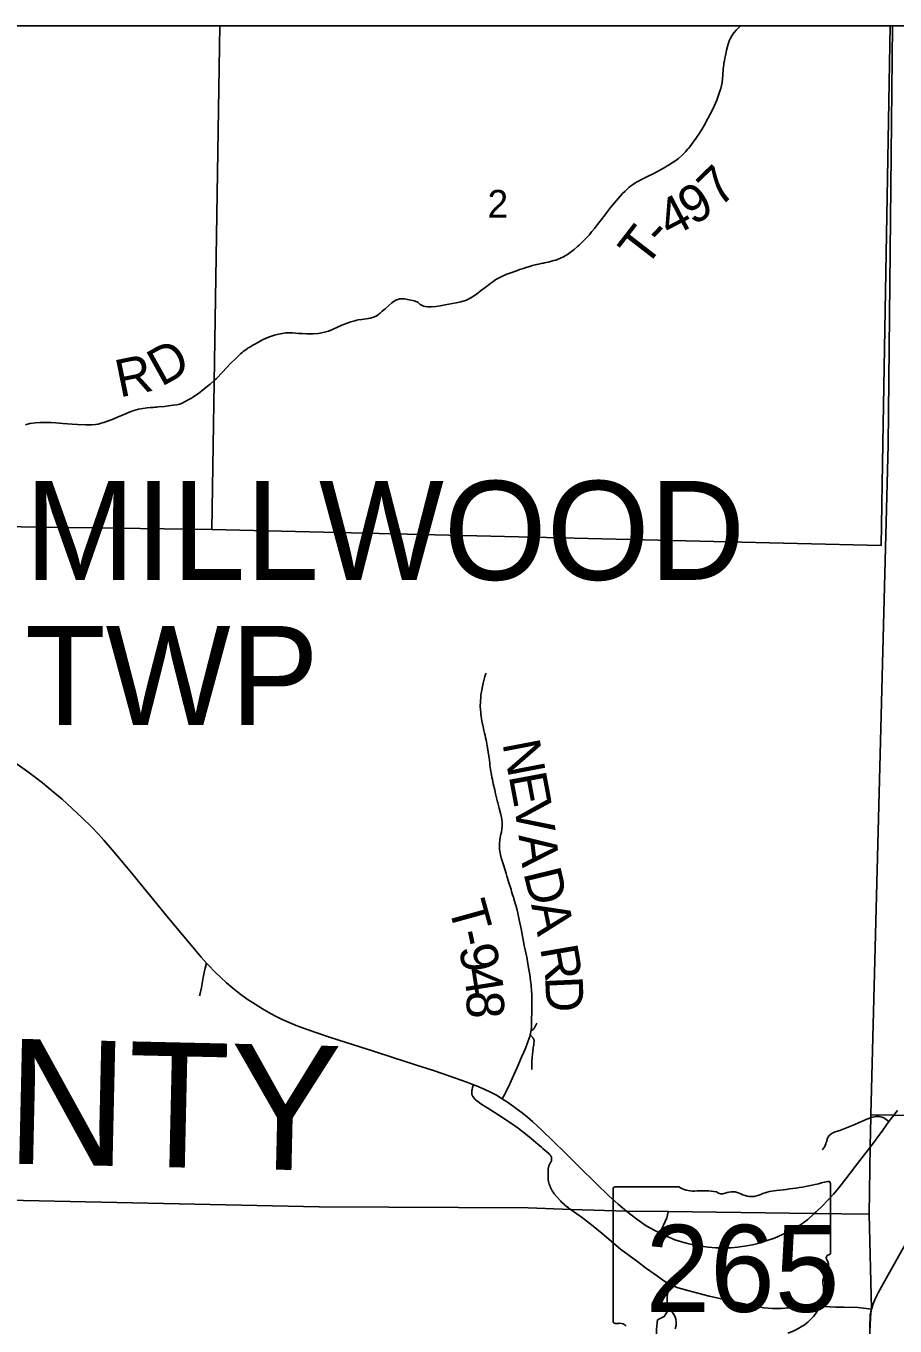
# Model space of a CAD drawing. Extents: x 0 to 34, y 0 to 22.
# Drawn here: x 5.917 to 7.235, y 18.929 to 20.9 of the extents above; entities that cross this region are included whole.
import ezdxf

# ---------------------------------------------------------------- set-up
doc = ezdxf.new("R2010")
doc.units = 0
for name, color, linetype in [('GM_X_Corporation', 7, 'Continuous'), ('GM_X_County_Text', 7, 'Continuous'), ('GM_X_Section_Text', 7, 'Continuous'), ('GM_X_State_Location', 7, 'Continuous'), ('GM_X_State_Route', 7, 'Continuous'), ('GM_X_State_Shield', 7, 'Continuous'), ('GM_X_Township_Road', 7, 'Continuous'), ('GM_X_Township_Road_Text', 7, 'Continuous'), ('GM_X_Township_Text', 7, 'Continuous'), ('SH_Data', 7, 'Continuous')]:
    doc.layers.add(name, color=color, linetype=linetype)

msp = doc.modelspace()

# ---------------------------------------------------------------- linework, layer by layer
at = {"layer": 'GM_X_Corporation'}
for points in [[(6.2111, 20.9), (5.1978, 20.9), (5.1859, 20.1511), (6.1991, 20.1367)], [(7.2273, 20.9), (6.2111, 20.9), (6.1991, 20.1367), (7.2139, 20.1126), (7.2163, 20.2673)], [(7.1227, 14.1), (8.9, 14.1), (8.9, 20.9), (7.231, 20.9), (7.2244, 20.2649), (7.1982, 19.2496), (7.1981, 19.2461), (7.1974, 19.2018), (7.1957, 19.0991), (7.1992, 18.9556), (7.197, 18.9465), (7.1949, 18.8464), (7.1846, 18.5133), (7.1817, 18.3306), (7.1804, 18.2238), (7.1572, 17.4131), (7.1504, 16.6562), (7.1434, 16.3848), (7.1318, 15.4937)], [(8.9, 19.2243), (8.9, 20.9), (7.231, 20.9), (7.2244, 20.2649), (7.1982, 19.2496), (7.2323, 19.2489), (7.3421, 19.2478), (7.6914, 19.2442), (7.7835, 19.2432)]]:
    msp.add_lwpolyline(points, close=True, dxfattribs=at)
at = {"layer": 'GM_X_State_Route'}
for points in [[(5.8954, 19.7869), (5.9197, 19.7697), (5.9318, 19.761), (5.9421, 19.753), (5.9555, 19.7419), (5.972, 19.7278), (5.9872, 19.7141), (6.003, 19.6992), (6.0163, 19.6861), (6.027, 19.675), (6.0354, 19.6658), (6.048, 19.6512), (6.0747, 19.6193), (6.095, 19.5945)], [(6.095, 19.5945), (6.1108, 19.5751), (6.1334, 19.5477), (6.1651, 19.5095), (6.1829, 19.4887), (6.1911, 19.4795), (6.1941, 19.4762), (6.2035, 19.4663), (6.2124, 19.4575), (6.2211, 19.4496), (6.2307, 19.4415), (6.241, 19.4335), (6.2526, 19.4251), (6.2645, 19.4172), (6.2756, 19.4102), (6.2842, 19.4052), (6.2947, 19.3997), (6.3058, 19.3942), (6.316, 19.3895), (6.327, 19.3851), (6.3433, 19.379), (6.3757, 19.3679), (6.3916, 19.3625), (6.4443, 19.3459), (6.4733, 19.3365), (6.5064, 19.3259), (6.5365, 19.316), (6.5683, 19.3053), (6.5858, 19.299), (6.5957, 19.2952), (6.6003, 19.2934), (6.6117, 19.2886), (6.6217, 19.2838), (6.6305, 19.2792), (6.6393, 19.2738), (6.6488, 19.2676), (6.6604, 19.2593), (6.6693, 19.2527), (6.6775, 19.2461), (6.6859, 19.2388), (6.6995, 19.2261), (6.7347, 19.1919), (6.7558, 19.1709), (6.781, 19.146), (6.8011, 19.1266), (6.8149, 19.114), (6.8282, 19.1028)], [(7.1976, 19.2012), (7.2163, 19.2264), (7.2257, 19.2392), (7.2387, 19.2562)], [(7.2, 18.9571), (7.2002, 18.9582), (7.2019, 18.9631), (7.2043, 18.969), (7.2067, 18.9745), (7.2092, 18.9796), (7.2221, 19.0025), (7.2453, 19.0437), (7.2581, 19.0668), (7.2751, 19.0967), (7.2881, 19.1201), (7.299, 19.1387), (7.3085, 19.1542), (7.3147, 19.1649), (7.3202, 19.175), (7.3242, 19.1834), (7.3275, 19.1912), (7.3306, 19.1997), (7.3336, 19.2087), (7.3364, 19.2185), (7.3385, 19.2275), (7.3402, 19.2356), (7.3415, 19.2442), (7.3427, 19.2553)], [(7.1117, 19.0994), (7.1152, 19.1025), (7.1252, 19.1119), (7.1322, 19.119), (7.1414, 19.1292), (7.1499, 19.1391), (7.1604, 19.1523), (7.1813, 19.1802), (7.1976, 19.2012)], [(6.8282, 19.1028), (6.8433, 19.0913), (6.8575, 19.0815), (6.8781, 19.0703), (6.8855, 19.0666), (6.8921, 19.0639), (6.9011, 19.0603), (6.9113, 19.0571), (6.9222, 19.054), (6.9338, 19.0516), (6.9518, 19.0489), (6.9632, 19.048), (6.9753, 19.0477), (6.9857, 19.048), (6.996, 19.049), (7.0065, 19.0503), (7.0188, 19.0526), (7.0307, 19.0555), (7.0408, 19.0588), (7.0519, 19.0626), (7.0644, 19.0679), (7.0739, 19.0726), (7.0836, 19.0782), (7.0915, 19.083), (7.1026, 19.0907), (7.1117, 19.0994)], [(7.1966, 18.921), (7.1971, 18.9313), (7.1978, 18.9417), (7.1984, 18.9489), (7.1994, 18.9551), (7.2, 18.9571)]]:
    msp.add_lwpolyline(points, dxfattribs=at)
at = {"layer": 'GM_X_State_Shield'}
for p, q in [((6.8074, 19.1369), (6.8074, 18.9368)), ((6.9072, 19.1403), (6.8107, 19.1403)), ((7.137, 19.0406), (7.137, 19.1453)), ((7.137, 19.0406), (7.137, 19.0406))]:
    msp.add_line(p, q, dxfattribs=at)
for centre, major_axis, start_param, end_param in [((6.8112, 19.1373), (0.00382, 0), 1.712693, 3.28349), ((6.9302, 19.1636), (0.037, 0), 4.042523, 4.731795), ((6.9424, 19.028), (0.133, 0), 1.404758, 1.657858), ((6.9883, 19.1152), (0.0222, 0), 0.950623, 2.079405), ((7.0642, 19.0792), (0.0703, 0), 1.699011, 2.107814), ((7.0196, 19.4132), (0.3495, 0), 4.814394, 5.042369), ((7.1333, 19.1457), (0.00367, 0), 6.141152, 7.989035), ((6.9726, 19.1384), (0.0107, 0), 3.836095, 5.185415), ((7.017, 19.147), (0.0267, 0), 4.081561, 5.145723), ((7.1361, 19.0329), (0.00568, 0), 1.883978, 3.671073), ((7.1331, 19.0402), (0.00393, 0), 5.05454, 6.418171), ((7.1, 19.0197), (0.0341, 0), 5.934695, 6.695948), ((7.1501, 18.9968), (0.0248, 0), 2.387724, 3.262537), ((7.0392, 18.9835), (0.0874, 0), 5.101752, 6.440018), ((6.8112, 18.9363), (0.00385, 0), 3.00124, 4.508301), ((6.8118, 18.9568), (0.0294, 0), 4.665946, 4.897461), ((6.8178, 18.9252), (0.0106, 0), 0.519207, 1.627899)]:
    msp.add_ellipse(centre, major_axis=major_axis, ratio=0.8, start_param=start_param, end_param=end_param, dxfattribs=at)
at = {"layer": 'GM_X_Township_Road'}
for points in [[(5.9162, 20.2956), (5.9228, 20.2972), (5.9314, 20.2986), (5.9382, 20.299), (5.9419, 20.299), (5.945, 20.299), (5.9487, 20.2988), (5.9555, 20.2988), (5.9617, 20.2985), (5.9679, 20.2981), (5.9728, 20.2975), (5.9874, 20.2963), (5.9952, 20.2958), (6.0079, 20.2953), (6.0164, 20.2953), (6.0224, 20.2958), (6.0267, 20.2965), (6.0314, 20.2977), (6.035, 20.2988), (6.0408, 20.3009), (6.0478, 20.3035), (6.0557, 20.3069), (6.0619, 20.3097), (6.0669, 20.3118), (6.075, 20.3151), (6.0808, 20.3171), (6.088, 20.319), (6.0941, 20.3201), (6.1008, 20.321), (6.1057, 20.3215), (6.11, 20.3219), (6.1125, 20.3221), (6.1155, 20.3223), (6.118, 20.3225), (6.1272, 20.3233), (6.1332, 20.324), (6.1399, 20.325), (6.1461, 20.3259), (6.1498, 20.3268), (6.1528, 20.328), (6.1642, 20.3339), (6.1679, 20.336), (6.1712, 20.3378), (6.1748, 20.3402), (6.1788, 20.3431), (6.1876, 20.3499), (6.1942, 20.3553), (6.1965, 20.3571), (6.202, 20.362), (6.206, 20.3658), (6.2149, 20.3753), (6.2274, 20.3883), (6.2357, 20.3966), (6.2382, 20.3991), (6.2399, 20.4007), (6.2408, 20.4014), (6.2425, 20.403), (6.2443, 20.4046), (6.2466, 20.4065), (6.248, 20.4076), (6.2505, 20.4093), (6.2523, 20.4107), (6.2533, 20.4114), (6.2554, 20.4126), (6.2623, 20.4167), (6.266, 20.4188), (6.2676, 20.4197), (6.2697, 20.4209), (6.2724, 20.4223), (6.275, 20.4238), (6.2777, 20.4253), (6.2788, 20.4258), (6.2877, 20.4292), (6.294, 20.4312), (6.2999, 20.4327), (6.3059, 20.4341), (6.3107, 20.4349), (6.3151, 20.4351), (6.3212, 20.4349), (6.3305, 20.4341), (6.3367, 20.4337), (6.3429, 20.4333), (6.3478, 20.4333), (6.3526, 20.4333), (6.3601, 20.4338), (6.3631, 20.4342), (6.3698, 20.4357), (6.3757, 20.4376), (6.3821, 20.4401), (6.3905, 20.444), (6.3984, 20.4476), (6.4095, 20.4514), (6.416, 20.4533), (6.4186, 20.454), (6.4207, 20.4545), (6.4263, 20.4553), (6.4362, 20.4565), (6.4398, 20.4572), (6.444, 20.4584), (6.4479, 20.4602), (6.4515, 20.4626), (6.4529, 20.4637), (6.4543, 20.4648), (6.4575, 20.4677), (6.4617, 20.4714), (6.4674, 20.4762), (6.4719, 20.4804), (6.4755, 20.483), (6.4782, 20.4845), (6.481, 20.4856), (6.4841, 20.4863), (6.4871, 20.4865), (6.4909, 20.4863), (6.4958, 20.4855), (6.5006, 20.4844), (6.5061, 20.4833), (6.5084, 20.4826), (6.5101, 20.4818), (6.5116, 20.4808), (6.5148, 20.4779), (6.5169, 20.4766), (6.5198, 20.4753), (6.5228, 20.4746), (6.5265, 20.4742), (6.5314, 20.4742), (6.5388, 20.4747), (6.545, 20.4756), (6.5529, 20.4772), (6.5693, 20.4804), (6.5766, 20.4821), (6.5795, 20.4828), (6.5819, 20.4835), (6.5853, 20.4846), (6.5887, 20.4862), (6.5919, 20.4881), (6.5956, 20.4904), (6.5976, 20.4918), (6.5996, 20.4932), (6.6026, 20.4955), (6.6055, 20.4977), (6.6085, 20.5), (6.6109, 20.5018), (6.6139, 20.5041), (6.6168, 20.5063), (6.6193, 20.5081), (6.6218, 20.5099), (6.6248, 20.512), (6.6298, 20.5156), (6.6345, 20.5184), (6.6405, 20.5214), (6.6462, 20.5238), (6.6538, 20.5263), (6.6607, 20.529), (6.6624, 20.5296), (6.6636, 20.5301), (6.6653, 20.5307), (6.6677, 20.5315), (6.6694, 20.532), (6.6741, 20.5335), (6.6823, 20.5361), (6.6852, 20.5369), (6.6894, 20.5379), (6.6917, 20.5385), (6.6986, 20.54), (6.7008, 20.5404), (6.7019, 20.5406), (6.7035, 20.5409), (6.7059, 20.5414), (6.7088, 20.5421), (6.7112, 20.5426), (6.7142, 20.5434), (6.7177, 20.5444), (6.7206, 20.5452), (6.7241, 20.5465), (6.7275, 20.5478), (6.732, 20.55), (6.7347, 20.5515), (6.7384, 20.5537), (6.7425, 20.5565), (6.7444, 20.558), (6.7484, 20.561), (6.7536, 20.5655), (6.7558, 20.5675), (6.7585, 20.5701), (6.7621, 20.5736), (6.7655, 20.5771), (6.7685, 20.5803), (6.7714, 20.5835), (6.7738, 20.5864), (6.7753, 20.5883), (6.7792, 20.5931), (6.7808, 20.595), (6.7838, 20.599), (6.7947, 20.6132), (6.7989, 20.6187), (6.8034, 20.6246), (6.8124, 20.6356), (6.8186, 20.6427), (6.8218, 20.646), (6.8255, 20.6498), (6.8315, 20.6552), (6.834, 20.6573), (6.8369, 20.6594), (6.8404, 20.6617), (6.8437, 20.6637), (6.8513, 20.6679), (6.8597, 20.672), (6.8692, 20.6766), (6.8736, 20.6788), (6.8768, 20.6806), (6.8784, 20.6814), (6.8848, 20.685), (6.8879, 20.6869), (6.8916, 20.6891), (6.8984, 20.6935), (6.9025, 20.6963), (6.9065, 20.6992), (6.9116, 20.7037), (6.9143, 20.7063), (6.9172, 20.7094), (6.9209, 20.7136), (6.9221, 20.715), (6.9237, 20.7169), (6.929, 20.7238), (6.933, 20.7295), (6.9351, 20.7326), (6.9376, 20.7362), (6.9419, 20.7432), (6.9454, 20.7492), (6.9511, 20.7598), (6.9564, 20.7697), (6.9607, 20.7786), (6.9627, 20.7831), (6.9646, 20.7877), (6.9664, 20.7923), (6.9694, 20.801), (6.9707, 20.8052), (6.972, 20.8099), (6.9727, 20.8142), (6.9736, 20.8252), (6.9744, 20.8351), (6.9748, 20.8388), (6.9751, 20.8406), (6.9754, 20.8431), (6.9758, 20.8455), (6.9761, 20.8474), (6.9768, 20.851), (6.9776, 20.8552), (6.9793, 20.8631), (6.9809, 20.8691), (6.9836, 20.8773), (6.9852, 20.8814), (6.9874, 20.8852), (6.9906, 20.8897), (6.9938, 20.8935), (6.9973, 20.897), (7.0007, 20.9)], [(6.683, 19.377), (6.6835, 19.3838), (6.6838, 19.3919), (6.6842, 19.4074), (6.6844, 19.418), (6.6843, 19.4285), (6.6842, 19.4328), (6.6839, 19.4366), (6.6831, 19.4464), (6.6823, 19.4524), (6.6811, 19.4615), (6.6788, 19.4756), (6.6765, 19.4885), (6.6755, 19.4933), (6.6728, 19.5061), (6.6711, 19.5146), (6.6678, 19.5317), (6.6652, 19.5451), (6.663, 19.5554), (6.6614, 19.562), (6.6599, 19.5672), (6.6591, 19.5701), (6.6581, 19.5736), (6.6571, 19.5771), (6.6563, 19.5795), (6.6551, 19.5829), (6.654, 19.5864), (6.6535, 19.5882), (6.6527, 19.5911), (6.6518, 19.594), (6.6509, 19.597), (6.65, 19.5999), (6.6465, 19.6112), (6.6451, 19.6153), (6.641, 19.6283), (6.6378, 19.639), (6.6366, 19.6437), (6.6354, 19.6517), (6.635, 19.6566), (6.635, 19.6597), (6.6359, 19.6671), (6.6374, 19.675), (6.638, 19.678), (6.6388, 19.6829), (6.6393, 19.6878), (6.6393, 19.6922), (6.6388, 19.6971), (6.6382, 19.7001), (6.6372, 19.7048), (6.6347, 19.7144), (6.6326, 19.7222), (6.6322, 19.724), (6.6312, 19.7282), (6.6293, 19.736), (6.6279, 19.742), (6.6257, 19.751), (6.6243, 19.7577), (6.6236, 19.7607), (6.6228, 19.765), (6.6216, 19.7729), (6.6212, 19.776), (6.6207, 19.7803), (6.6204, 19.7827), (6.6194, 19.7907), (6.6191, 19.7931), (6.6185, 19.7967), (6.6177, 19.8021), (6.6171, 19.8057), (6.6169, 19.8069), (6.6166, 19.8087), (6.616, 19.8117), (6.6148, 19.8177), (6.614, 19.8213), (6.6132, 19.8249), (6.6125, 19.828), (6.6115, 19.8322), (6.6103, 19.8376), (6.6086, 19.8462), (6.6079, 19.8504), (6.6075, 19.8535), (6.6071, 19.8566), (6.6067, 19.8596), (6.606, 19.8683), (6.6061, 19.8758), (6.6067, 19.8832), (6.6071, 19.8862), (6.6078, 19.8905), (6.6083, 19.8935), (6.6089, 19.8965), (6.6104, 19.9038), (6.612, 19.9098), (6.6131, 19.914), (6.614, 19.9169), (6.6148, 19.9192)], [(6.1804, 19.4297), (6.1814, 19.4334), (6.1833, 19.4425), (6.1858, 19.4579), (6.1872, 19.4652), (6.189, 19.4718), (6.1911, 19.4795)], [(6.6393, 19.2738), (6.6431, 19.2808), (6.6443, 19.2829), (6.647, 19.2885), (6.6486, 19.2919), (6.6567, 19.31), (6.6617, 19.3214), (6.6683, 19.3367), (6.672, 19.3446), (6.675, 19.3518), (6.6777, 19.3586), (6.6803, 19.3659), (6.6811, 19.3681), (6.6818, 19.3707)], [(6.6818, 19.3707), (6.6822, 19.3721), (6.6829, 19.3758), (6.683, 19.377)], [(6.6845, 19.3181), (6.6844, 19.319), (6.6843, 19.3206), (6.6842, 19.3268), (6.6842, 19.331), (6.6846, 19.3365), (6.6852, 19.3414), (6.6857, 19.3457), (6.6864, 19.3512), (6.6869, 19.3541), (6.687, 19.3553), (6.6874, 19.3589), (6.6875, 19.3608), (6.6875, 19.362), (6.6873, 19.3629), (6.6871, 19.3637), (6.6867, 19.3645), (6.6863, 19.3653), (6.6859, 19.3658), (6.6855, 19.3665), (6.6818, 19.3707)], [(6.683, 19.377), (6.6838, 19.3773), (6.6848, 19.3778), (6.6859, 19.3786), (6.6864, 19.3791), (6.6869, 19.3797), (6.6875, 19.3805), (6.688, 19.3813), (6.6917, 19.3884)], [(6.6273, 19.2534), (6.6215, 19.2571), (6.6068, 19.2664), (6.6022, 19.2696), (6.6004, 19.2711), (6.5989, 19.2724), (6.5977, 19.2735), (6.5967, 19.2746), (6.5949, 19.2772), (6.5943, 19.2783), (6.5939, 19.2794), (6.5934, 19.2805), (6.5931, 19.2817), (6.593, 19.2825), (6.593, 19.2841), (6.5932, 19.2862), (6.5935, 19.2879), (6.5943, 19.2908), (6.5954, 19.294), (6.5957, 19.2952)], [(6.7438, 19.1055), (6.7415, 19.1072), (6.7396, 19.1086), (6.7364, 19.1111), (6.7343, 19.1128), (6.7325, 19.1144), (6.7304, 19.1163), (6.7281, 19.1186), (6.7223, 19.1251), (6.7183, 19.1299), (6.7164, 19.1325), (6.7152, 19.1345), (6.714, 19.1364), (6.713, 19.1383), (6.7121, 19.1403), (6.7114, 19.1423), (6.7107, 19.1444), (6.7102, 19.1464), (6.7097, 19.1483), (6.7092, 19.1508), (6.709, 19.153), (6.7089, 19.1556), (6.7089, 19.1631), (6.709, 19.1647), (6.709, 19.1663), (6.709, 19.1673), (6.7091, 19.1684), (6.7093, 19.1694), (6.7095, 19.1705), (6.7098, 19.1714), (6.7102, 19.1725), (6.7106, 19.1734), (6.711, 19.1744), (6.7125, 19.1772), (6.7129, 19.178), (6.7133, 19.1788), (6.7138, 19.18), (6.7141, 19.181), (6.7142, 19.1819), (6.7142, 19.183), (6.7141, 19.1841), (6.7138, 19.1852), (6.7134, 19.1863), (6.7128, 19.1872), (6.7122, 19.1882), (6.7114, 19.1891), (6.7105, 19.1902), (6.7094, 19.1912), (6.705, 19.1952), (6.7008, 19.1987), (6.6989, 19.2003), (6.6956, 19.2031), (6.6938, 19.2048), (6.6834, 19.2136), (6.6728, 19.2222), (6.6687, 19.2254), (6.6633, 19.2293), (6.6517, 19.2375), (6.6341, 19.2491), (6.6273, 19.2534)], [(7.1244, 19.1965), (7.1254, 19.1977), (7.1269, 19.1994), (7.1283, 19.2014), (7.1291, 19.2031), (7.1299, 19.2055), (7.1307, 19.2078), (7.1313, 19.2095), (7.1317, 19.2107), (7.1319, 19.2118), (7.1322, 19.2131), (7.1326, 19.214), (7.1328, 19.2149), (7.1333, 19.2157), (7.1337, 19.2165), (7.1353, 19.2184), (7.1372, 19.2201), (7.1384, 19.2209), (7.1398, 19.2218), (7.1411, 19.2224), (7.1426, 19.2231), (7.1441, 19.2236), (7.1514, 19.226), (7.1613, 19.2296), (7.1715, 19.2339), (7.1828, 19.2389), (7.1923, 19.2429), (7.1951, 19.2439), (7.1983, 19.2456)], [(7.1983, 19.2456), (7.2013, 19.2462), (7.204, 19.2466), (7.2064, 19.2468), (7.2107, 19.2468)], [(7.2107, 19.2468), (7.2128, 19.2465), (7.2147, 19.2462), (7.2165, 19.2457), (7.2179, 19.245), (7.2193, 19.2441), (7.2217, 19.2424), (7.2257, 19.2392)], [(6.7438, 19.1055), (6.7609, 19.0935), (6.7772, 19.0806), (6.7909, 19.0696), (6.8185, 19.0458), (6.8448, 19.0266), (6.8567, 19.0177), (6.8746, 19.0051), (6.8844, 18.9981), (6.8953, 18.9914), (6.9062, 18.9872), (6.9206, 18.9834), (6.9357, 18.9793), (6.9531, 18.9748), (6.9737, 18.9699), (6.9941, 18.9655), (7.036, 18.9572), (7.0489, 18.9559), (7.0624, 18.9558), (7.0872, 18.9579), (7.105, 18.9591), (7.1261, 18.9589), (7.145, 18.9582), (7.1571, 18.9582), (7.1792, 18.9573), (7.1994, 18.9551)], [(6.8781, 19.0703), (6.8889, 19.0934), (6.8909, 19.1025)], [(6.9017, 18.9249), (6.9029, 18.9303), (6.9031, 18.9351), (6.9023, 18.9404), (6.9006, 18.9453), (6.8975, 18.9501), (6.8931, 18.9567), (6.8912, 18.9599), (6.8895, 18.9658), (6.8893, 18.9731), (6.8901, 18.9789), (6.8917, 18.9845), (6.8953, 18.9914)], [(6.8195, 18.8077), (6.8278, 18.8146), (6.8423, 18.8299), (6.849, 18.84), (6.8553, 18.8537), (6.8582, 18.8585), (6.8675, 18.8714), (6.8742, 18.8858), (6.8755, 18.8913), (6.873, 18.9075), (6.8733, 18.9245), (6.8748, 18.9387), (6.885, 18.9438), (6.8931, 18.9567)]]:
    msp.add_lwpolyline(points, dxfattribs=at)
at = {"layer": 'GM_X_Township_Text'}
for points in [[(2.1, 19.1775), (2.6044, 19.174), (2.6249, 19.1744), (2.7359, 19.1727), (3.4968, 19.1598), (3.523, 19.1623), (4.1413, 19.1495), (4.1773, 19.1491), (4.6334, 19.1433), (5.5591, 19.1275), (6.3618, 19.1099), (6.6786, 19.1086), (6.7436, 19.1061), (6.828, 19.1033), (6.8907, 19.103), (7.1115, 19.0999), (7.1957, 19.0991), (7.1974, 19.2018), (7.1981, 19.2461), (7.1982, 19.2496), (7.2244, 20.2649), (7.231, 20.9)], [(7.231, 20.9), (2.1, 20.9), (2.1, 19.1775)], [(7.231, 20.9), (8.9, 20.9), (8.9, 19.2243)], [(7.1227, 14.1), (8.9, 14.1), (8.9, 19.2243), (7.7835, 19.2432), (7.6914, 19.2442), (7.3421, 19.2478), (7.2323, 19.2489), (7.1982, 19.2496)], [(7.1227, 14.1), (7.1318, 15.4937), (7.1434, 16.3848), (7.1504, 16.6562), (7.1572, 17.4131), (7.1804, 18.2238), (7.1817, 18.3306), (7.1846, 18.5133), (7.1949, 18.8464), (7.197, 18.9465), (7.1992, 18.9556), (7.1957, 19.0991), (7.1536, 19.0995)]]:
    msp.add_lwpolyline(points, dxfattribs=at)
at = {"layer": 'SH_Data'}
msp.add_line((2.1, 20.9), (8.9, 20.9), dxfattribs=at)

# ---------------------------------------------------------------- texts
at = {"layer": 'GM_X_County_Text'}
msp.add_text('GUERNSEY COUNTY', height=0.189394, rotation=358.7038, dxfattribs=at).set_placement((3.8321, 19.2222))
at = {"layer": 'GM_X_Section_Text'}
msp.add_text('2', height=0.0419, rotation=0, dxfattribs=at).set_placement((6.6171, 20.6096))
at = {"layer": 'GM_X_State_Location'}
for s in ['s', 'r']:
    msp.add_text(s, height=0.000189, dxfattribs=at).set_placement((6.9685, 19.0235))
msp.add_text('265', height=0.000189, rotation=0, dxfattribs=at).set_placement((6.9016, 19.0098))
at = {"layer": 'GM_X_State_Shield'}
msp.add_text('265', height=0.13184, dxfattribs=at).set_placement((6.8565, 18.9509))
at = {"layer": 'GM_X_Township_Road_Text'}
for s, rotation, p in [('7', 44.2781, (6.9691, 20.6232)), ('9', 31.7988, (6.9287, 20.5965)), ('4', 27.4308, (6.8936, 20.578)), ('T', 52.2772, (6.8565, 20.5316)), ('-', 46.5291, (6.8815, 20.5641)), ('D', 29.0913, (6.1223, 20.3525)), ('R', 11.5128, (6.0591, 20.3367)), ('N', 280.8842, (6.6394, 19.8127)), ('E', 280.5854, (6.6489, 19.7636)), ('V', 278.5119, (6.6566, 19.7224)), ('A', 276.7916, (6.6639, 19.6734)), ('D', 283.7084, (6.6712, 19.6164)), ('T', 285.4562, (6.5572, 19.566)), ('A', 281.9551, (6.6829, 19.5682)), ('-', 282.0631, (6.5683, 19.5259)), ('9', 281.2395, (6.5731, 19.5033)), ('R', 279.7421, (6.6966, 19.5027)), ('4', 279.0037, (6.5798, 19.4696)), ('D', 272.5654, (6.7043, 19.4586)), ('8', 270.6609, (6.5851, 19.4372))]:
    msp.add_text(s, height=0.0568, rotation=rotation, dxfattribs=at).set_placement(p)
at = {"layer": 'GM_X_Township_Text'}
for s, p in [('MILLWOOD', (5.9155, 20.0604)), ('TWP', (5.9155, 19.8404))]:
    msp.add_text(s, height=0.15, rotation=0, dxfattribs=at).set_placement(p)

doc.saveas('drawing.dxf')
